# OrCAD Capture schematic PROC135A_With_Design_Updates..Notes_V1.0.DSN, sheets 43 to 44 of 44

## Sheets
43 43. CAN_FD_WKUP_SW: size C; title: CAN FD WKUP SW
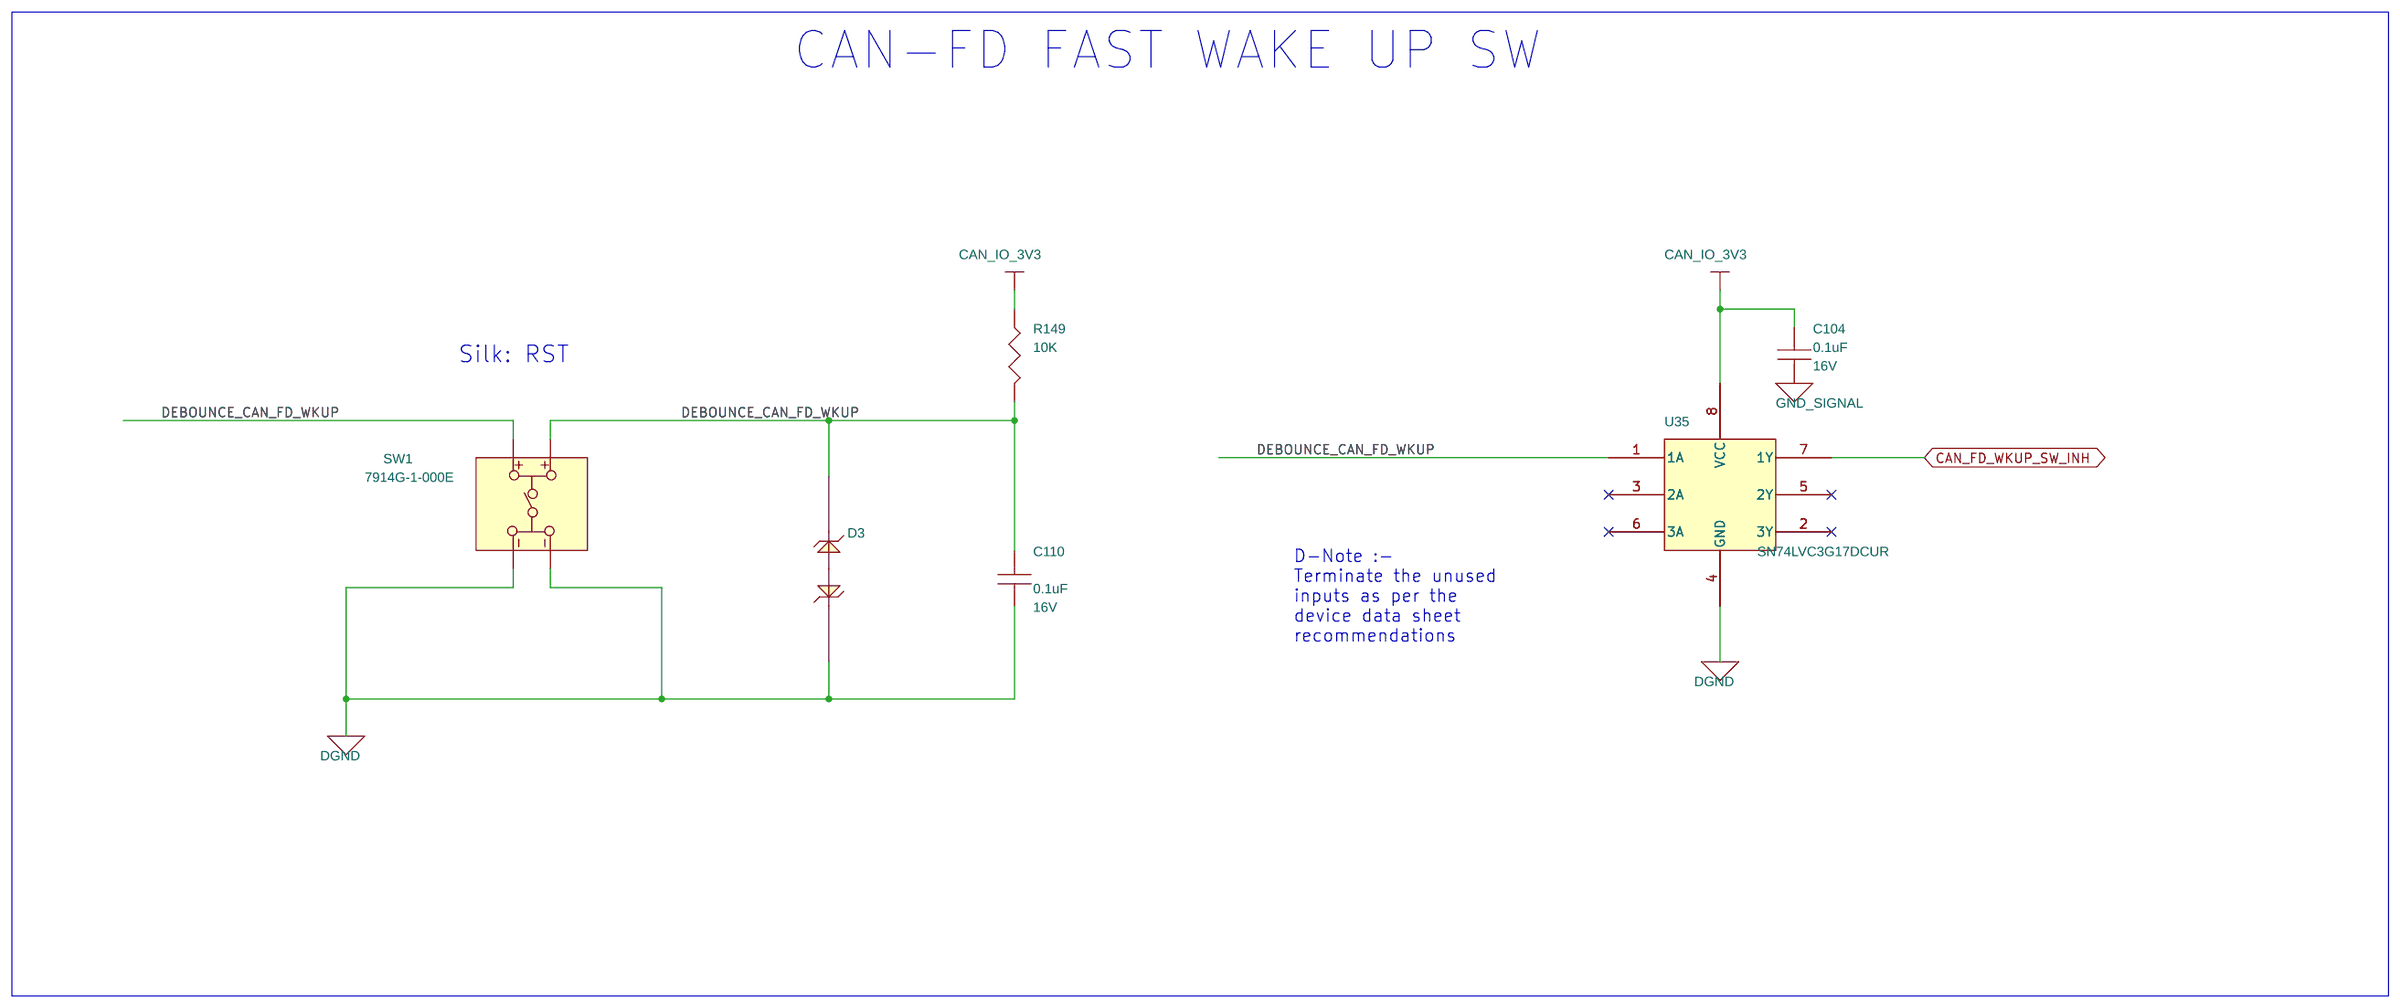
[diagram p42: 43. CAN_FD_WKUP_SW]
44 44. ACCESSORIES: title: HARDWARE SCHEMATICS
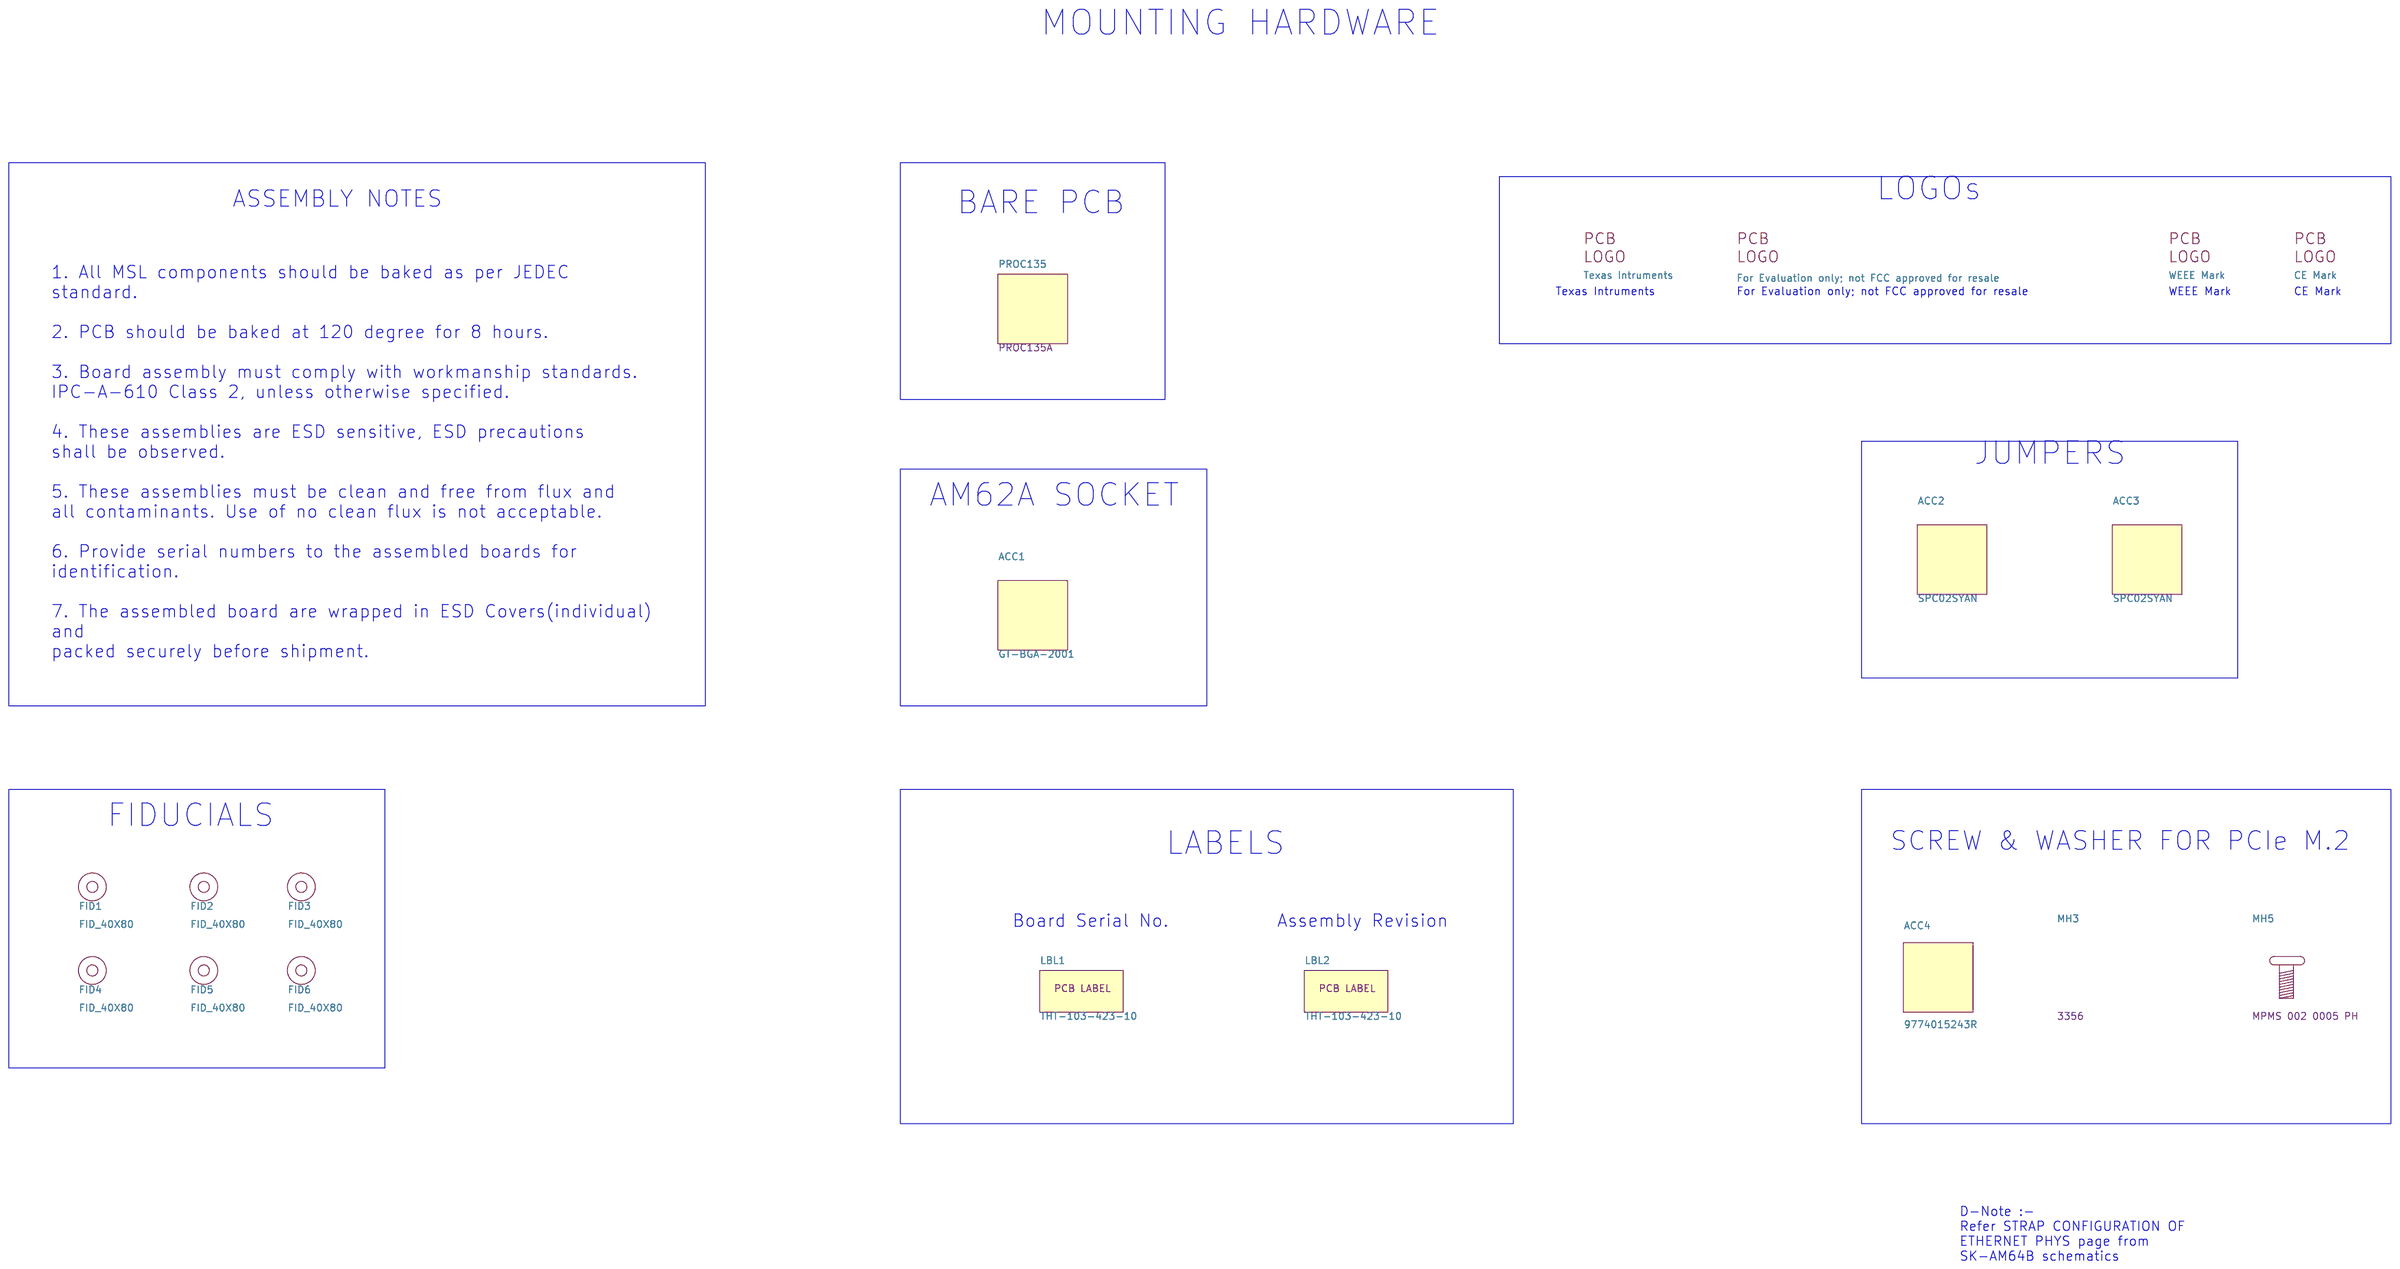
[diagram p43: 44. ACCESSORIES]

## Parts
sheet 43. CAN_FD_WKUP_SW
C104  0.1uF  [CAP0201_0-5]
C110  0.1uF  [CAP0201_0-5]
D3  TPD1E10B06DPYR  [DIO_DFN0402_0-5]
R149  10K  [RES0201_0-5]
SW1  7914G-1-000E  [SW4_100X216_200X200_SMD_4-2]
U35  SN74LVC3G17DCUR  [VSSOP8_19-68_85X95_0-9]
sheet 44. ACCESSORIES
ACC1  GT-BGA-2001  [BGASKT484_GT-BGA-2001_910X910_10-7]
ACC2  SPC02SYAN  [NA]
ACC3  SPC02SYAN  [NA]
ACC4  9774015243R  [NA]
FID1  FID_40X80  [FID_40X80]
FID2  FID_40X80  [FID_40X80]
FID3  FID_40X80  [FID_40X80]
FID4  FID_40X80  [FID_40X80]
FID5  FID_40X80  [FID_40X80]
FID6  FID_40X80  [FID_40X80]
LBL1  THT-103-423-10  [NA]
LBL2  THT-103-423-10  [NA]
LOGO1  Texas Intruments  [TI_Stacked_Overlay_Small]
LOGO2  For Evaluation only; not FCC approved for resale  [FCC_disclaimer]
LOGO3  WEEE Mark  [TI_Stacked_Overlay_Small]
LOGO4  CE Mark  [TI_Stacked_Overlay_Small]
MH3  FLAT WASHER_M2  [NA]
MH5  PAN HEAD_M2 X 5  [NA]
PCB1  PROC135

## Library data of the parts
C104 C110 = CAP: CAP CERAMIC 0.1uF 16V 10% X5R 0201; Alt_Mfr_name: YAGEO AMERICA; Alt_Mfr_part_number: CC0402KRX5R8BB104; Chkd/date: MANIRAJA/230118; Crtd /date: MANIRAJA/230118; Custom_Duty: 15%; Customs_HS_Code: 85322990; Distributor_name: DIGIKEY; Distributor_part_number: 490-14305-1-ND; Footprint Path: Y:\MIS_DATABASE\Library\ALTIUM_TOOL\PCB_FOOTPRINTS\Altium_Footprint_Lib.PcbLib; Height: 0.33MM; Library Path: Y:\MIS_DATABASE\Library\ALTIUM_TOOL\SCHEMATICS_PARTS\MS_DISCRETE_Library.schlib; Mfr_name: MURATA; Mfr_part_number: GRM033R61C104KE14D; Mistral Part No: 120009030072-R; Package: 0201; Part_type: CAPACITORS\CERAMIC; Project: TI_MAXIE_CPB; RoHS: RoHS; Temperature: -55°C+85°C; Tolerance: 10%; Voltage: 16V; Wattage: NA; Weight: 0.33mg; Datasheet: Y:\MIS_DATABASE\DATASHEETS\CAPACITORS\GRM033R61C104KE14.PDF
D3 = DIODE_SOD323: DIODE 1CH ESD PROTECTION X1SON2; Chkd/date: MANIRAJA/040420; Crtd /date: VASANTHA/181114; Custom_Duty: 15%; Customs_HS_Code: 85423100; Distributor_name: DIGIKEY; Distributor_part_number: 296-30406-1-ND; Footprint Path: Y:\MIS_DATABASE\Library\ALTIUM_TOOL\PCB_FOOTPRINTS\Altium_Footprint_Lib.PcbLib; Height: 0.45MM; Library Path: Y:\MIS_DATABASE\Library\ALTIUM_TOOL\SCHEMATICS_PARTS\MS_DISCRETE_Library.schlib; Mfr_name: TEXAS INSTRUMENTS; Mistral Part No: 130014110022-R; Package: X1SON2; Part_type: DIODE; Project: GALILEO_EVM; RoHS: RoHS; Temperature: -40°C+125°C; Tolerance: NA; Voltage: NA; Wattage: NA; Weight: 1mg; Datasheet: Y:\MIS_DATABASE\DATASHEETS\ICS\INTERFACE\TPD1E10B06-SER.PDF
R149 = RESISTOR: RES 10K 1/20W 5% 0201; Chkd/date: MANIRAJA/050517; Crtd /date: MANIRAJA/050517; Custom_Duty: 15%; Customs_HS_Code: 85332119; Distributor_name: DIGIKEY; Distributor_part_number: 311-10KNCT-ND; Footprint Path: Y:\MIS_DATABASE\Library\ALTIUM_TOOL\PCB_FOOTPRINTS\Altium_Footprint_Lib.PcbLib; Height: 0.26MM; Library Path: Y:\MIS_DATABASE\Library\ALTIUM_TOOL\SCHEMATICS_PARTS\MS_DISCRETE_Library.schlib; Mfr_name: YAGEO AMERICA; Mfr_part_number: RC0201JR-0710KL; Mistral Part No: 110010070051-R; Package: 0201; Part_type: RESISTORS\FIXED; Project: GOLDEN-I LITE; RoHS: RoHS; Temperature: -55°C+125°C; Tolerance: 5%; Voltage: NA; Wattage: 1/20W; Weight: 0.17mg; Datasheet: Y:\MIS_DATABASE\DATASHEETS\RESISTORS\RCXXXXL-SER_MAR18.PDF
SW1 = 7914G-1-000E__7914G: SWITCH SPST-NO 4MM SQ SMD 7914G; Chkd/date: VASANTHA/271216; Crtd /date: BAVISH/051010; Custom_Duty: 24%; Customs_HS_Code: 85369090; Distributor_name: DIGIKEY; Distributor_part_number: 7914G-000ECT-ND; Height: 4.19MM; Library Ref: 7914G-1-000E _7914G; Mfr_name: BOURNS; Mistral Part No: 130015110004-R; Package: 7914G; Part_type: ELECTRO-MECHANICAL\SWITCH; Project: AAAUC; RoHS: RoHS; Temperature: -55°C+125°C; Tolerance: NA; Voltage: NA; Wattage: NA; Weight: NA; Datasheet: Y:\MIS_DATABASE\DATASHEETS\ICS\DIGITAL\COMBINATIONAL\7914G-1-000E.PDF
U35 = SN74LVC3G17DCUR_VSSOP8: IC TRIPLE SCHMITT-TRIGGER BUFFER VSSOP8; Chkd/date: MANIRAJA/280917; Crtd /date: MANIRAJA/280917; Custom_Duty: 15%; Customs_HS_Code: 85423100; Distributor_name: DIGIKEY; Distributor_part_number: 296-18818-1-ND; Height: 0.90MM; Mfr_name: TEXAS INSTRUMENTS; Mistral Part No: 141017090019-R; Package: VSSOP8; Part_type: ICS\DIGITAL\COMBINATIONAL; Project: TI_MAXIE_CPB; RoHS: RoHS; Temperature: -40°C+125°C; Tolerance: NA; Voltage: NA; Wattage: NA; Weight: 9.6mg; Datasheet: Y:\MIS_DATABASE\DATASHEETS\ICS\DIGITAL\COMBINATIONAL\SN74LVC3G17.PDF
ACC1 = ACCESSORY: ACCESSORIE BGA SOCKET AM62A SVB SoC MICROPROCESSOR FCBGA484; Chkd/date: ALVY/180422; Crtd /date: ALVY/180422; Custom_Duty: NA; Customs_HS_Code: NA; Distributor_name: NA; Distributor_part_number: NA; Footprint Path: NA; Height: 10.69MM; Library Path: NA; Mfr_name: IRONWOOD ELECTRONICS; Mistral Part No: 160022040013; Package: FCBGA484; Part_type: ACCESSORIES; Project: TI_AM62A_SVB_BRD; RoHS: NA; Temperature: NA; Tolerance: NA; Voltage: NA; Wattage: NA; Weight: NA; Datasheet: Y:\MIS_DATABASE\DATASHEETS\MISC\ACCESSORIES\GT-BGA-2001.PDF
ACC2 ACC3 = ACCESSORY: ACCESSORIE JUMPER SHORTING GOLD FLASH; Chkd/date: SUHAS\211010; Crtd /date: USMAN/301208; Distributor_name: DIGIKEY; Distributor_part_number: S9001-ND; Footprint Path: Y:\MIS_DATABASE\Library\ALTIUM_TOOL\PCB_FOOTPRINTS\Altium_Footprint_Lib.PcbLib; Library Path: Y:\MIS_DATABASE\Library\ALTIUM_TOOL\SCHEMATICS_PARTS\MS_MECHANICAL_Library.schlib; Mfr_name: SULLINS CONNECTOR; Mistral Part No: 160009030153-R; Part_type: ACCESSORIES; Project: SMART VIEW_NVR; RoHS: RoHS; Temperature: -55°C+105°C; Datasheet: Y:\MIS_DATABASE\DATASHEETS\MISC\MODULES\SPC02SYAN.PDF
ACC4 = ACCESSORY: STANDOFF BOARD TO BOARD 1.50MM LENGTH FEMALE M2 THREADED SS; Chkd/date: MANIRAJA/280219; Crtd /date: ALVY/280219; Distributor_name: DIGIKEY; Distributor_part_number: 732-7069-1-ND; Mfr_name: WURTH ELECTRONICS; Mistral Part No: 160019020049-R; Package: SS; Part_type: MECHANICAL\STANDOFF; Project: TI_J7ES_EVM_CP; RoHS: RoHS; Weight: 178mg; Datasheet: Y:\MIS_DATABASE\DATASHEETS\MISC\MECHANICAL\9774015243R.PDF
FID1-FID6 = Fiducial
LBL1 LBL2 = ACCESSORY_THT-3-423-10: ACCESSORIE 1 WORKHORSE POLYSTER LABLE 0.25" X 1"; Chkd/date: MANIRAJA/270218; Crtd /date: ALVY/260218; Footprint Path: Y:\MIS_DATABASE\Library\ALTIUM_TOOL\PCB_FOOTPRINTS\Altium_Footprint_Lib.PcbLib; Library Path: Y:\MIS_DATABASE\Library\ALTIUM_TOOL\SCHEMATICS_PARTS\MS_MECHANICAL_Library.schlib; Mfr_name: BRADY; Mistral Part No: 160018020185; Part_type: ACCESSORIES; Project: TI_MAXIE_CPB
LOGO1 LOGO3 LOGO4 = TI_Logo
LOGO2 = FCC_disclaimer
MH3 = WASHER_FLAT: FLAT WASHER FOR M2 NYLON; Chkd/date: MANIRAJA/110319; Crtd /date: ALVY/110319; Distributor_name: DIGIKEY; Distributor_part_number: 36-3356-ND; Mfr_name: KEYSTONE; Mfr_part_number: 3356; Mistral Part No: 160019030017-R; Package: NYLON; Part_type: MECHANICAL\WASHERS; Project: TI_J7ES_EVM_CP; RoHS: RoHS; Datasheet: Y:\MIS_DATABASE\DATASHEETS\MISC\MECHANICAL\3356.PDF
MH5 = SCREW_PAN: PHILLIPS PAN HEAD SCREW - M2 X 5; Chkd/date: MANIRAJA/150319; Crtd /date: MANIRAJA/150319; Distributor_name: DIGIKEY; Distributor_part_number: H738-ND; Height: 5.00MM; Mfr_name: B AND F FASTENER; Mfr_part_number: MPMS 002 0005 PH; Mistral Part No: 160019030026-R; Part_type: MECHANICAL\SCREWS; Project: TI_J7ES_EVM_CP; RoHS: RoHS; Datasheet: Y:\MIS_DATABASE\DATASHEETS\MISC\MECHANICAL\SCREW_MPMSXXX.PDF
PCB1 = PCB_0: AM62A SKEVM; Mfr_part_number: PROC135A; Mistral Part No: FY22-23/00176000401

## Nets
DGND: C104.2 C110.1 D3.1 SW1.1 SW1.4 U35.4(GND) ; also on sheet 9 10 11 12 13 14 15 16 17 18 19 20 21 22 23 24 25 26 27 28 29 30 31 32 33 34 35 36 37 38 39 40 41 42
CAN_FD_WKUP_SW_INH: U35.7(1Y) ; also on sheet 33
CAN_IO_3V3: C104.1 R149.1 U35.8(VCC) ; also on sheet 12 14 30 33
DEBOUNCE_CAN_FD_WKUP: C110.2 D3.2 R149.2 SW1.2 SW1.3 U35.1(1A)

Not connected (* = marked no-connect by the designer): U35 2(3Y)* 3(2A)* 5(2Y)* 6(3A)*

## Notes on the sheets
sheet 43
- CAN-FD FAST WAKE UP SW
- Silk: RST
- D-Note :-
  Terminate the unused
  inputs as per the
  device data sheet
  recommendations
sheet 44
- MOUNTING HARDWARE
- LOGOs
- ASSEMBLY NOTES
- BARE PCB
- 1. All MSL components should be baked as per JEDEC
  standard.
  2. PCB should be baked at 120 degree for 8 hours.
  3. Board assembly must comply with workmanship standards.
  IPC-A-610 Class 2, unless otherwise specified.
  4. These assemblies are ESD sensitive, ESD precautions
  shall be observed.
  5. These assemblies must be clean and free from flux and
  all contaminants. Use of no clean flux is not acceptable.
  6. Provide serial numbers to the assembled boards for
  identification.
  7. The assembled board are wrapped in ESD Covers(individual)
  and
  packed securely before shipment.
- Texas Intruments
- For Evaluation only; not FCC approved for resale
- WEEE Mark
- CE Mark
- JUMPERS
- AM62A SOCKET
- FIDUCIALS
- LABELS
- SCREW & WASHER FOR PCIe M.2
- Board Serial No.
- Assembly Revision
- D-Note :-
  Refer STRAP CONFIGURATION OF
  ETHERNET PHYS page from
  SK-AM64B schematics
